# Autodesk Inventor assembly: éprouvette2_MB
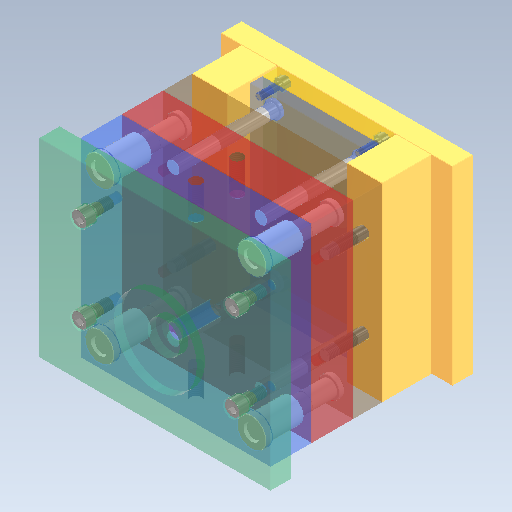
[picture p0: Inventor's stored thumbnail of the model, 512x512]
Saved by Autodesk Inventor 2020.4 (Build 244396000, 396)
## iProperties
Created: 2021-10
Part Number: éprouvette2_MB
Document SubType Name: Assembly
Designer: mel
Author: mel
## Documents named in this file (16)
- D:\travail\année 2020-2021\itec\prépa injection plastique eduscol\dossier de travail\Ensemble des pièces de l'activité\Conception de moule1\Mo\FUTABA_SA-S 2\éprouvette2_MB.iam
- C:\Users\mel\Documents\Inventor\Content Center Files\R2020\fr-FR\JIS 1176\JIS 1176 M8x25.ipt
- C:\Users\mel\Documents\Inventor\Content Center Files\R2020\fr-FR\GBA\M-GBA 20x49.ipt
- D:\travail\année 2020-2021\itec\prépa injection plastique eduscol\dossier de travail\Ensemble des pièces de l'activité\Conception de moule1\Mo\FUTABA_SA-S 2\éprouvette2_MB_SA-SB1.ipt
- D:\travail\année 2020-2021\itec\prépa injection plastique eduscol\dossier de travail\Ensemble des pièces de l'activité\Conception de moule1\Mo\FUTABA_SA-S 2\éprouvette2_MB_SA-SB2.ipt
- D:\travail\année 2020-2021\itec\prépa injection plastique eduscol\dossier de travail\Ensemble des pièces de l'activité\Conception de moule1\Mo\FUTABA_SA-S 2\éprouvette2_MB_SA-EP.ipt
- C:\Users\mel\Documents\Inventor\Content Center Files\R2020\fr-FR\GPA\M-GPA20x97x39.ipt
- D:\travail\année 2020-2021\itec\prépa injection plastique eduscol\dossier de travail\Ensemble des pièces de l'activité\Conception de moule1\Mo\FUTABA_SA-S 2\éprouvette2_MB_SA-ERP.ipt
- D:\travail\année 2020-2021\itec\prépa injection plastique eduscol\dossier de travail\Ensemble des pièces de l'activité\Conception de moule1\Mo\FUTABA_SA-S 2\éprouvette2_MB_SA-BCP.ipt
- C:\Users\mel\Documents\Inventor\Content Center Files\R2020\fr-FR\JIS 1176\JIS 1176 M12x25.ipt
- D:\travail\année 2020-2021\itec\prépa injection plastique eduscol\dossier de travail\Ensemble des pièces de l'activité\Conception de moule1\Mo\FUTABA_SA-S 2\éprouvette2_MB_RPN.ipt
- D:\travail\année 2020-2021\itec\prépa injection plastique eduscol\dossier de travail\Ensemble des pièces de l'activité\Conception de moule1\Mo\FUTABA_SA-S 2\éprouvette2_MB_SA-S-AP.ipt
- D:\travail\année 2020-2021\itec\prépa injection plastique eduscol\dossier de travail\Ensemble des pièces de l'activité\Conception de moule1\Mo\FUTABA_SA-S 2\éprouvette2_MB_SA-S-BP.ipt
- D:\travail\année 2020-2021\itec\prépa injection plastique eduscol\dossier de travail\Ensemble des pièces de l'activité\Conception de moule1\Mo\FUTABA_SA-S 2\éprouvette2_MB_SA-TCP.ipt
- D:\travail\année 2020-2021\itec\prépa injection plastique eduscol\dossier de travail\Ensemble des pièces de l'activité\Conception de moule1\Mo\FUTABA_SA-S 2\éprouvette2_MB_SA-SP.ipt
- C:\Users\mel\Documents\Inventor\Content Center Files\R2020\fr-FR\JIS 1176\JIS 1176 M12x120.ipt
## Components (33 placed, 15 different names)
1. éprouvette2_MB_SA-SB1:1 — Affleurement:1, Affleurement:3, Placage:1, Placage:5
2. éprouvette2_MB_SA-SB2:2 — Affleurement:2, Affleurement:4, Placage:2, Placage:6
3. éprouvette2_MB_SA-EP:1 — Logement:1, Affleurement:5, Affleurement:6, Ejection, Placage:4
4. éprouvette2_MB_SA-ERP:1 — Logement:7, Affleurement:7, Affleurement:8, Placage:4
5. éprouvette2_MB_SA-BCP:1 — Logement:8, Ejection, Affleurement:9, Affleurement:10, Placage:5, Placage:6
6. éprouvette2_MB_SA-S-AP:1 — Logement:2, Logement:5, Affleurement:11, Affleurement:12, Placage:7, PL1, Affleurement:19
7. éprouvette2_MB_SA-S-BP:1 — Logement:3, Logement:4, Affleurement:13, Affleurement:14, PL1, Placage:9
8. éprouvette2_MB_SA-TCP:1 — Logement:6, Placage:7, Affleurement:15, Affleurement:16
9. éprouvette2_MB_SA-SP:1 — Placage:1, Placage:2, Affleurement:17, Affleurement:18, Placage:9
10. GPA 20x97x39:1 — Logement:3
11. GPA 20x97x39:3
12. JIS 1176 M12x25:1 — Logement:6
13. JIS 1176 M12x25:2
14. JIS 1176 M12x25:3
15. JIS 1176 M12x25:4
16. JIS 1176 M8x25:1 — Logement:1
17. JIS 1176 M8x25:2
18. JIS 1176 M8x25:3
19. JIS 1176 M8x25:4
20. JIS 1176 M12x120:1 — Logement:8
21. JIS 1176 M12x120:2
22. JIS 1176 M12x120:3
23. JIS 1176 M12x120:4
24. GBA 20x49:1 — Logement:2
25. GBA 20x49:3
26. GPA 20x97x39:2 — Logement:4
27. GPA 20x97x39:4
28. éprouvette2_MB_RPN:1 — Logement:7
29. éprouvette2_MB_RPN:2
30. éprouvette2_MB_RPN:3
31. éprouvette2_MB_RPN:4
32. GBA 20x49:2 — Logement:5
33. GBA 20x49:4
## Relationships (36: Flush 19, Mate 9, Insert 8)
- Logement:1 [Insert]: éprouvette2_MB_SA-EP:1 ↔ JIS 1176 M8x25:1
- Logement:2 [Insert]: éprouvette2_MB_SA-S-AP:1 ↔ GBA 20x49:1
- Logement:3 [Insert]: éprouvette2_MB_SA-S-BP:1 ↔ GPA 20x97x39:1
- Logement:4 [Insert]: éprouvette2_MB_SA-S-BP:1 ↔ GPA 20x97x39:2
- Logement:5 [Insert]: éprouvette2_MB_SA-S-AP:1 ↔ GBA 20x49:2
- Logement:6 [Insert]: éprouvette2_MB_SA-TCP:1 ↔ JIS 1176 M12x25:1
- Logement:7 [Insert]: éprouvette2_MB_SA-ERP:1 ↔ éprouvette2_MB_RPN:1
- Logement:8 [Insert]: éprouvette2_MB_SA-BCP:1 ↔ JIS 1176 M12x120:1
- Affleurement:1 [Flush]: éprouvette2_MB_SA-SB1:1
- Affleurement:2 [Flush]: éprouvette2_MB_SA-SB2:2
- Affleurement:3 [Flush]: éprouvette2_MB_SA-SB1:1
- Affleurement:4 [Flush]: éprouvette2_MB_SA-SB2:2
- Placage:1 [Mate]: éprouvette2_MB_SA-SB1:1 ↔ éprouvette2_MB_SA-SP:1
- Placage:2 [Mate]: éprouvette2_MB_SA-SB2:2 ↔ éprouvette2_MB_SA-SP:1
- Affleurement:5 [Flush]: éprouvette2_MB_SA-EP:1
- Affleurement:6 [Flush]: éprouvette2_MB_SA-EP:1
- Ejection [Mate]: éprouvette2_MB_SA-EP:1 ↔ éprouvette2_MB_SA-BCP:1
- Affleurement:7 [Flush]: éprouvette2_MB_SA-ERP:1
- Affleurement:8 [Flush]: éprouvette2_MB_SA-ERP:1
- Placage:4 [Mate]: éprouvette2_MB_SA-EP:1 ↔ éprouvette2_MB_SA-ERP:1
- Affleurement:9 [Flush]: éprouvette2_MB_SA-BCP:1
- Affleurement:10 [Flush]: éprouvette2_MB_SA-BCP:1
- Placage:5 [Mate]: éprouvette2_MB_SA-SB1:1 ↔ éprouvette2_MB_SA-BCP:1
- Placage:6 [Mate]: éprouvette2_MB_SA-SB2:2 ↔ éprouvette2_MB_SA-BCP:1
- Affleurement:11 [Flush]: éprouvette2_MB_SA-S-AP:1
- Affleurement:12 [Flush]: éprouvette2_MB_SA-S-AP:1
- Placage:7 [Mate]: éprouvette2_MB_SA-S-AP:1 ↔ éprouvette2_MB_SA-TCP:1
- Affleurement:13 [Flush]: éprouvette2_MB_SA-S-BP:1
- Affleurement:14 [Flush]: éprouvette2_MB_SA-S-BP:1
- PL1 [Mate]: éprouvette2_MB_SA-S-AP:1 ↔ éprouvette2_MB_SA-S-BP:1
- Affleurement:15 [Flush]: éprouvette2_MB_SA-TCP:1
- Affleurement:16 [Flush]: éprouvette2_MB_SA-TCP:1
- Affleurement:17 [Flush]: éprouvette2_MB_SA-SP:1
- Affleurement:18 [Flush]: éprouvette2_MB_SA-SP:1
- Placage:9 [Mate]: éprouvette2_MB_SA-S-BP:1 ↔ éprouvette2_MB_SA-SP:1
- Affleurement:19 [Flush]: éprouvette2_MB_SA-S-AP:1
